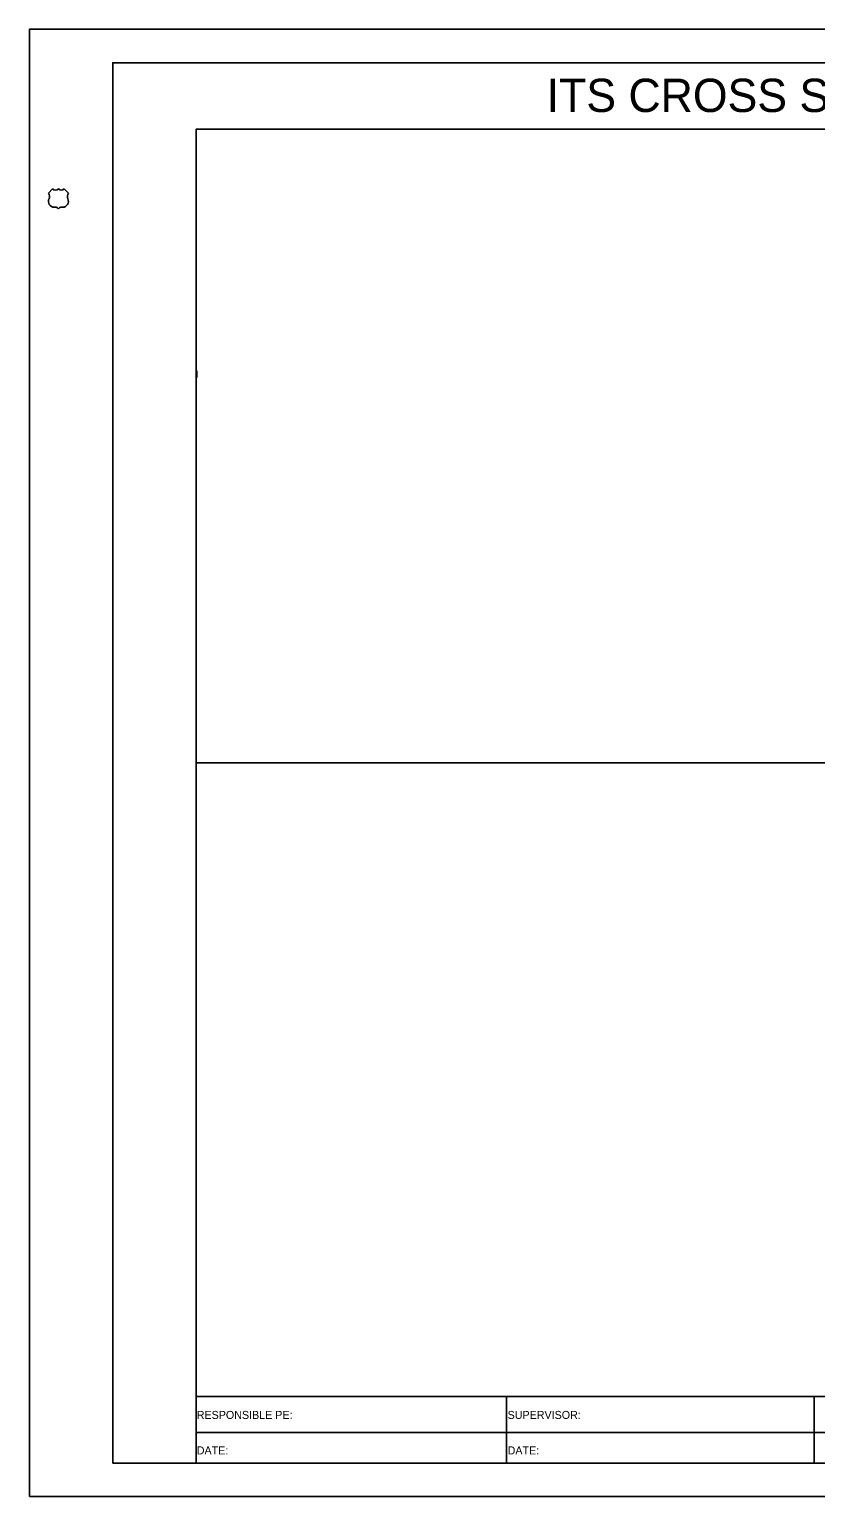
# Model space of a CAD drawing. Extents: x 2193008 to 2198143, y 1236112 to 1237864.
# Drawn here: x 2195203.8 to 2195321.7, y 1237118 to 1237338 of the extents above; entities that cross this region are included whole.
import ezdxf

# ---------------------------------------------------------------- set-up
doc = ezdxf.new("R2010")
doc.units = 0
for name, color, linetype in [('2', 7, 'Continuous'), ('3', 7, 'Continuous'), ('ANNO-SHT', 7, 'Continuous'), ('ANNO-TXT', 7, 'Continuous'), ('AXIS', 7, 'Continuous'), ('GSOUTLINE', 7, 'Continuous'), ('Level 62', 7, 'Continuous'), ('SHT-BDR', 7, 'Continuous'), ('SHT-BNDRY', 7, 'Continuous')]:
    doc.layers.add(name, color=color, linetype=linetype)

msp = doc.modelspace()

# ---------------------------------------------------------------- linework, layer by layer
at = {"layer": '2'}
msp.add_lwpolyline([(2195228.9, 1237286.82), (2195228.88, 1237285.82)], dxfattribs=at)
msp.add_lwpolyline([(2195228.9, 1237286.82), (2195228.88, 1237285.82)], dxfattribs=at)
at = {"layer": '3'}
msp.add_line((2195228.78, 1237228.05), (2195528.78, 1237228.05), dxfattribs=at)
at = {"layer": 'AXIS'}
msp.add_line((2195228.78, 1237243.04), (2195228.78, 1237243.05), dxfattribs=at)
at = {"layer": 'GSOUTLINE'}
for points in [[(2195207.27, 1237314.11), (2195206.65, 1237313.49)], [(2195209.65, 1237313.49), (2195209.02, 1237314.11)], [(2195207.52, 1237311.37), (2195207.65, 1237311.37)], [(2195208.65, 1237311.37), (2195208.77, 1237311.37)]]:
    msp.add_lwpolyline(points, dxfattribs=at)
for centre, major_axis, start_param, end_param in [((2195205.94, 1237312.98), (0.875, 0), 5.853097, 6.905662), ((2195207.71, 1237314.56), (0.625, 0), 3.936991, 5.487786), ((2195208.58, 1237314.56), (0.625, 0), 3.936991, 5.487786), ((2195210.36, 1237312.98), (0.875, 0), 2.519116, 3.571681), ((2195207.52, 1237312.24), (0.875, 0), 2.698682, 4.712389), ((2195207.65, 1237310.75), (0.625, 0), 0.643501, 1.570796), ((2195208.65, 1237310.75), (0.625, 0), 1.570796, 2.498092), ((2195208.77, 1237312.24), (0.875, 0), 4.712389, 6.726096)]:
    msp.add_ellipse(centre, major_axis=major_axis, ratio=0.997059, start_param=start_param, end_param=end_param, dxfattribs=at)
at = {"layer": 'Level 62'}
msp.add_lwpolyline([(2195203.79, 1237118.04), (2195543.79, 1237118.04), (2195543.79, 1237338.04), (2195203.79, 1237338.04)], close=True, dxfattribs=at)
at = {"layer": 'SHT-BDR'}
msp.add_lwpolyline([(2195228.78, 1237133.05), (2195528.78, 1237133.05), (2195528.78, 1237323.05), (2195228.78, 1237323.05)], close=True, dxfattribs=at)
at = {"layer": 'SHT-BNDRY'}
for p, q in [((2195228.78, 1237123.04), (2195228.78, 1237133.05)), ((2195275.31, 1237133.05), (2195275.31, 1237123.04)), ((2195321.45, 1237123.04), (2195321.45, 1237133.05)), ((2195228.78, 1237127.65), (2195384.41, 1237127.65))]:
    msp.add_line(p, q, dxfattribs=at)
msp.add_lwpolyline([(2195216.29, 1237123.04), (2195538.79, 1237123.04), (2195538.79, 1237333.04), (2195216.29, 1237333.04)], close=True, dxfattribs=at)

# ---------------------------------------------------------------- texts
at = {"layer": 'ANNO-SHT'}
msp.add_text('              ITS CROSS SECTIONS               ', height=4.9995, rotation=360, dxfattribs=at).set_placement((2195255.33, 1237325.64))
at = {"layer": 'ANNO-TXT'}
for s, p in [('RESPONSIBLE PE:', (2195228.88, 1237129.69)), ('SUPERVISOR:', (2195275.48, 1237129.69)), ('DATE:', (2195228.88, 1237124.37)), ('DATE:', (2195275.48, 1237124.37))]:
    msp.add_text(s, height=1.2, rotation=360, dxfattribs=at).set_placement(p)

doc.saveas('drawing.dxf')
